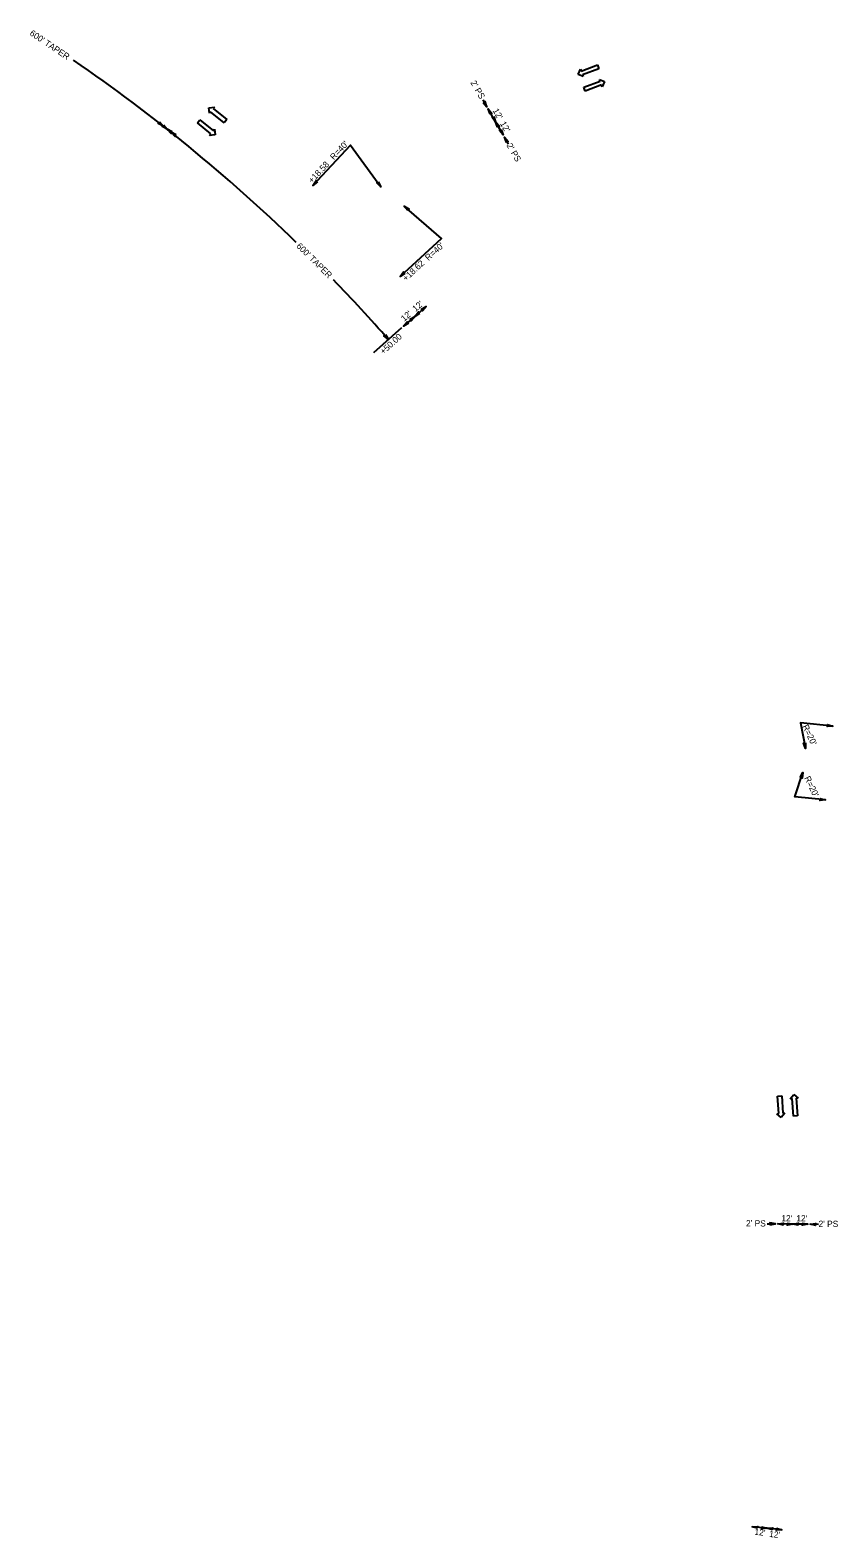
# Model space of a CAD drawing. Extents: x 2320991 to 2332664, y 598057 to 612602.
# Drawn here: x 2326817 to 2327464, y 600566 to 601773 of the extents above; entities that cross this region are included whole.
import ezdxf

# ---------------------------------------------------------------- set-up
doc = ezdxf.new("R2010")
doc.units = 0
for name, color, linetype in [('Prop Dimension', 7, 'Continuous'), ('Prop Dimension Text', 7, 'Continuous'), ('Prop Lane Arrow CELL', 7, 'Continuous'), ('Prop Terminator CELL', 7, 'Continuous')]:
    doc.layers.add(name, color=color, linetype=linetype)

msp = doc.modelspace()

# ---------------------------------------------------------------- linework, layer by layer
at = {"layer": 'Prop Dimension'}
for p, q in [((2327179.6, 601717.7), (2327182.8, 601712.1)), ((2327189.8, 601699.9), (2327183.8, 601710.3)), ((2327195.8, 601689.5), (2327189.8, 601699.9)), ((2327200, 601682.1), (2327196.8, 601687.8)), ((2327125, 601544.1), (2327116, 601536.2)), ((2327134.1, 601552), (2327125, 601544.1)), ((2327114.5, 601534.9), (2327091.9, 601515)), ((2327407.3, 600817), (2327413.8, 600817)), ((2327427.8, 600816.9), (2327415.8, 600817)), ((2327439.8, 600816.8), (2327427.8, 600816.9)), ((2327448.3, 600816.7), (2327441.8, 600816.8)), ((2327407.1, 600573.2), (2327395.2, 600574.4)), ((2327419.1, 600572), (2327407.1, 600573.2))]:
    msp.add_line(p, q, dxfattribs=at)
for points in [[(2327043.5, 601649.1), (2327073.6, 601681.4), (2327097.8, 601647.9)], [(2327113.3, 601576), (2327146.4, 601606.6), (2327116.6, 601632.4)], [(2327459.8, 601215.9), (2327434, 601218.5), (2327438, 601198)], [(2327453.9, 601156.7), (2327429.3, 601159.2), (2327435.9, 601178.7)]]:
    msp.add_lwpolyline(points, dxfattribs=at)
for start, end in [(45.8023, 55.5916), (41.2493, 44.0109)]:
    msp.add_arc((2326088.9, 600635.5), 1350, start, end, dxfattribs=at)
at = {"layer": 'Prop Lane Arrow CELL'}
for p, q in [((2327255.9, 601738), (2327257.7, 601742.1)), ((2327259.9, 601736.2), (2327255.9, 601738)), ((2327257.7, 601742.1), (2327258.2, 601740.7)), ((2327258.2, 601740.7), (2327271.3, 601745.6)), ((2327272.5, 601742.5), (2327259.4, 601737.6)), ((2327259.4, 601737.6), (2327259.9, 601736.2)), ((2327271.3, 601745.6), (2327272.5, 601742.5)), ((2327260.3, 601727.7), (2327273.5, 601732.6)), ((2327261.5, 601724.6), (2327260.3, 601727.7)), ((2327274.6, 601729.6), (2327261.5, 601724.6)), ((2327273.5, 601732.6), (2327272.9, 601734)), ((2327272.9, 601734), (2327277, 601732.2)), ((2327275.1, 601728.1), (2327274.6, 601729.6)), ((2327277, 601732.2), (2327275.1, 601728.1)), ((2326950.9, 601699.2), (2326952.9, 601701.7)), ((2326952.9, 601701.7), (2326963.8, 601692.9)), ((2326960.1, 601711.3), (2326964.6, 601711.8)), ((2326960.6, 601706.9), (2326960.1, 601711.3)), ((2326961.5, 601708.1), (2326960.6, 601706.9)), ((2326972.4, 601699.2), (2326961.5, 601708.1)), ((2326964.6, 601711.8), (2326963.6, 601710.6)), ((2326963.6, 601710.6), (2326974.5, 601701.8)), ((2326974.5, 601701.8), (2326972.4, 601699.2)), ((2326961.7, 601690.3), (2326950.9, 601699.2)), ((2326960.7, 601689.1), (2326961.7, 601690.3)), ((2326965.2, 601689.6), (2326960.7, 601689.1)), ((2326963.8, 601692.9), (2326964.7, 601694)), ((2326964.7, 601694), (2326965.2, 601689.6)), ((2327415.6, 600919.4), (2327418.9, 600919.6)), ((2327416.6, 600905.4), (2327415.6, 600919.4)), ((2327418.9, 600919.6), (2327419.9, 600905.7)), ((2327425.8, 600917.4), (2327428.7, 600920.7)), ((2327427.3, 600917.5), (2327425.8, 600917.4)), ((2327428.3, 600903.5), (2327427.3, 600917.5)), ((2327428.7, 600920.7), (2327432.1, 600917.8)), ((2327432.1, 600917.8), (2327430.6, 600917.7)), ((2327430.6, 600917.7), (2327431.6, 600903.7)), ((2327415.1, 600905.3), (2327416.6, 600905.4)), ((2327418.5, 600902.4), (2327415.1, 600905.3)), ((2327421.4, 600905.8), (2327418.5, 600902.4)), ((2327419.9, 600905.7), (2327421.4, 600905.8)), ((2327431.6, 600903.7), (2327428.3, 600903.5))]:
    msp.add_line(p, q, dxfattribs=at)
at = {"layer": 'Prop Terminator CELL'}
for points in [[(2327179.9, 601715.6), (2327182.8, 601712.1), (2327181.3, 601716.4), (2327180.9, 601715.5)], [(2327185.4, 601706.1), (2327183.8, 601710.3), (2327186.8, 601706.8), (2327185.8, 601706.9)], [(2327188.2, 601704.2), (2327189.8, 601699.9), (2327186.9, 601703.5), (2327187.9, 601703.4)], [(2326920.6, 601700), (2326923.6, 601696.6), (2326919.5, 601698.8), (2326920.5, 601699)], [(2326923.7, 601697.5), (2326926.7, 601694.1), (2326922.7, 601696.3), (2326923.6, 601696.6)], [(2326930.7, 601692), (2326926.7, 601694.1), (2326929.8, 601690.7), (2326929.8, 601691.7)], [(2326933.9, 601689.6), (2326929.8, 601691.7), (2326933, 601688.3), (2326933, 601689.3)], [(2327191.4, 601695.6), (2327189.8, 601699.9), (2327192.8, 601696.4), (2327191.8, 601696.5)], [(2327194.2, 601693.8), (2327195.8, 601689.5), (2327192.8, 601693.1), (2327193.8, 601693)], [(2327198.4, 601683.5), (2327196.8, 601687.8), (2327199.7, 601684.3), (2327198.8, 601684.4)], [(2327047.1, 601651.9), (2327043.5, 601649.1), (2327046, 601653), (2327046.2, 601652)], [(2327095.8, 601652), (2327097.8, 601647.9), (2327094.5, 601651.1), (2327095.5, 601651.1)], [(2327119.5, 601628.9), (2327116.6, 601632.4), (2327120.5, 601630.1), (2327119.6, 601629.9)], [(2327117.1, 601578.5), (2327113.3, 601576), (2327116.1, 601579.7), (2327116.2, 601578.7)], [(2327121.1, 601541.8), (2327125, 601544.1), (2327122.2, 601540.6), (2327122.1, 601541.5)], [(2327128.9, 601546.5), (2327125, 601544.1), (2327127.9, 601547.7), (2327128, 601546.7)], [(2327130.2, 601549.7), (2327134.1, 601552), (2327131.2, 601548.5), (2327131.1, 601549.4)], [(2327119.9, 601538.6), (2327116, 601536.2), (2327118.9, 601539.8), (2327119, 601538.8)], [(2327101.5, 601529.5), (2327103.9, 601525.6), (2327100.3, 601528.5), (2327101.3, 601528.6)], [(2327455.4, 601217.1), (2327459.8, 601215.9), (2327455.2, 601215.6), (2327455.9, 601216.3)], [(2327437.9, 601202.5), (2327438, 601198), (2327436.3, 601202.3), (2327437.2, 601201.9)], [(2327433.7, 601174.6), (2327435.9, 601178.7), (2327435.2, 601174.1), (2327434.6, 601174.9)], [(2327449.5, 601158), (2327453.9, 601156.7), (2327449.3, 601156.4), (2327449.9, 601157.1)], [(2327409.3, 600816.2), (2327413.8, 600817), (2327409.3, 600817.8), (2327409.9, 600817)], [(2327420.3, 600816.1), (2327415.8, 600817), (2327420.3, 600817.7), (2327419.8, 600816.9)], [(2327423.3, 600817.7), (2327427.8, 600816.9), (2327423.3, 600816.1), (2327423.9, 600816.9)], [(2327432.3, 600816), (2327427.8, 600816.9), (2327432.3, 600817.6), (2327431.8, 600816.8)], [(2327435.3, 600817.6), (2327439.8, 600816.8), (2327435.3, 600816), (2327435.9, 600816.8)], [(2327446.3, 600815.9), (2327441.8, 600816.8), (2327446.3, 600817.5), (2327445.8, 600816.7)], [(2327399.6, 600573.2), (2327395.2, 600574.4), (2327399.8, 600574.7), (2327399.1, 600574)], [(2327402.7, 600574.4), (2327407.1, 600573.2), (2327402.6, 600572.9), (2327403.2, 600573.6)], [(2327411.5, 600572), (2327407.1, 600573.2), (2327411.7, 600573.5), (2327411.1, 600572.8)], [(2327414.7, 600573.2), (2327419.1, 600572), (2327414.5, 600571.7), (2327415.2, 600572.4)]]:
    msp.add_lwpolyline(points, close=True, dxfattribs=at)

# ---------------------------------------------------------------- texts
at = {"layer": 'Prop Dimension'}
for s, rotation, p in [('+18.58', 46.9545, (2327042.8, 601650.4)), ('+18.62', 42.7085, (2327118, 601572)), ('+50.00', 42.4789, (2327100, 601513.3))]:
    msp.add_text(s, height=5, rotation=rotation, dxfattribs=at).set_placement(p)
at = {"layer": 'Prop Dimension Text'}
for s, rotation, p in [("600' TAPER", 325.9282, (2326816.1, 601769.9)), ("2' PS", 299.9036, (2327169.4, 601731.4)), ("12'", 299.9036, (2327187.2, 601709)), ("12'", 299.9036, (2327193.1, 601698.6)), ("R=40'", 46.637, (2327060.2, 601669.1)), ("2' PS", 299.9036, (2327198.3, 601681.1)), ("600' TAPER", 315.3292, (2327029.8, 601600)), ("R=40'", 42.3859, (2327136, 601588.4)), ("12'", 41.1654, (2327125.7, 601547.6)), ("12'", 41.1654, (2327116.6, 601539.7)), ("R=20'", 295.2158, (2327435.3, 601215.7)), ("R=20'", 295.2158, (2327436.9, 601174.4)), ("2' PS", 359.6067, (2327390.3, 600815.1)), ("12'", 359.5584, (2327418.6, 600819.1)), ("12'", 359.5584, (2327430.6, 600819.1)), ("2' PS", 359.6067, (2327448.4, 600814.7)), ("12'", 354.2481, (2327396.9, 600568)), ("12'", 354.2481, (2327408.7, 600566.3))]:
    msp.add_text(s, height=5, rotation=rotation, dxfattribs=at).set_placement(p)

doc.saveas('drawing.dxf')
